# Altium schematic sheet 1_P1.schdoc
size 309 x 223 mm; Symbol: Sheet-Symbol_A4; Device: Sheet-Symbol_A4; Company: 嘉立创EDA; Version: V1.0; Page Size: A4; @Project Name: Magnetic robot_hkust_bi; @Page Count: 1; @Update Date: 2025-05-18; @Create Date: 2025-05-14; @Schematic Name: Schematic4; @Page No: 1; @Page Name: P1
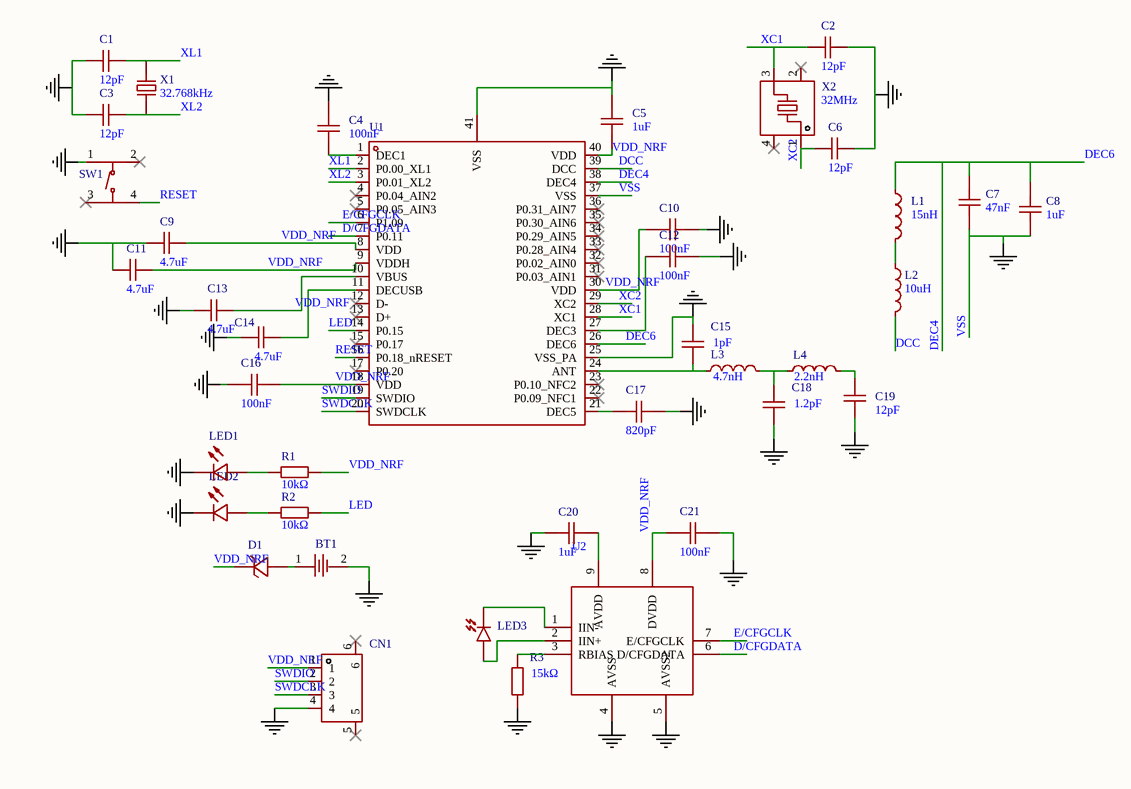
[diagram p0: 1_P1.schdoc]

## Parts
BT1  MY-927-01  [BAT-TH_MY-927-01]  (value not drawn)
C1  12pF  [C0402]
C2  12pF  [C0402]
C3  12pF  [C0402]
C4  100nF  [C0402]
C5  1uF  [C0402]
C6  12pF  [C0402]
C7  47nF  [C0402]
C8  1uF  [C0402]
C9  4.7uF  [C0402]
C10  100nF  [C0402]
C11  4.7uF  [C0402]
C12  100nF  [C0402]
C13  4.7uF  [C0402]
C14  4.7uF  [C0402]
C15  1pF  [C0402]
C16  100nF  [C0402]
C17  820pF  [C0402]
C18  1.2pF  [C0402]
C19  12pF  [C0402]
C20  1uF  [C0402]
C21  100nF  [C0402]
CN1  1.0-4PWB  [CONN-SMD_4P-P1.00_DEALON_1.0-4PWB]  (value not drawn)
D1  BZT52C3V3S  [SOD-323_L1.7-W1.3-LS2.6-RD]  (value not drawn)
L1  15nH  [IND-SMD_L1.0-W0.5-2]
L2  10uH  [IND-SMD_L2.5-W2.0]
L3  4.7nH  [IND-SMD_L1.0-W0.6]
L4  2.2nH  [IND-SMD_L1.0-W0.6]
LED1  NCD0603G1  [LED0603-RD_1]  (value not drawn)
LED2  NCD0603G1  [LED0603-RD_1]  (value not drawn)
LED3  VBPW34S  [SENSOR-SMD_L4.4-W3.9]  (value not drawn)
R1  10kΩ  [R0402]
R2  10kΩ  [R0402]
R3  15kΩ  [R0402]
SW1  TS-1187A-B-A-B  [SW-SMD_4P-L5.1-W5.1-P3.70-LS6.5-TL_H1.5]  (value not drawn)
U1  nRF52833-QDAA-R  [QFN-40_L5.0-W5.0-P0.40-TL-EP3.6]  (value not drawn)
U2  (no value)  [TS4231]
X1  32.768kHz  [OSC-SMD_L3.2-W1.5]
X2  32MHz  [CRYSTAL-SMD_4P-L2.0-W1.6-BL-2]

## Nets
VSS: BT1.2 C1.1 C2.2 C3.1 C4.2 C5.2 C6.2 C7.2 C8.2 C9.2 C10.2 C11.2 C12.2 C13.2 C14.1 C15.2 C16.1 C17.2 C18.1 C19.1 C20.1 C21.2 CN1.4 LED1.1(K) LED2.1(K) R3.1 SW1.1(A) U1.25(VSS_PA) U1.37(VSS) U1.41(VSS) U2.4(AVSS) U2.5(AVSS2)  [also labelled GND]
D/CFGDATA: U1.7(P0.11) U2.6(D/CFGDATA)
DCC: L2.2 U1.39(DCC)
DEC4: C7.1 C8.1 L1.2 U1.26(DEC6) U1.38(DEC4)  [also labelled DEC6]
E/CFGCLK: U1.6(P1.09) U2.7(E/CFGCLK)
LED: R2.2 U1.14(P0.15)
RESET: SW1.4(D) U1.16(P0.18_nRESET)
SWDCLK: CN1.3 U1.20(SWDCLK)
SWDIO: CN1.2 U1.19(SWDIO)
VDD_NRF: C5.1 C9.1 C10.1 C11.1 C13.1 C16.2 C21.1 CN1.1 D1.1(K) R1.2 U1.8(VDD) U1.9(VDDH) U1.10(VBUS) U1.18(VDD) U1.30(VDD) U1.40(VDD) U2.8(DVDD)
XC1: C2.1 U1.28(XC1) X2.3
XC2: C6.1 U1.29(XC2) X2.1
XL1: C1.2 U1.2(P0.00_XL1) X1.2
XL2: C3.2 U1.3(P0.01_XL2) X1.1
NetBT1_1: BT1.1 D1.2(A)
NetC4_1: C4.1 U1.1(DEC1)
NetC12_1: C12.1 U1.27(DEC3)
NetC14_2: C14.2 U1.11(DECUSB)
NetC15_1: C15.1 L3.1 U1.24(ANT)
NetC17_1: C17.1 U1.21(DEC5)
NetC18_2: C18.2 L3.2 L4.1
NetC19_2: C19.2 L4.2
NetC20_2: C20.2 U2.9(AVDD)
NetL1_1: L1.1 L2.1
NetLED1_2: LED1.2(A) R1.1
NetLED2_2: LED2.2(A) R2.1
NetLED3_1: LED3.1(A) U2.2(IIN+)
NetLED3_2: LED3.2(C) U2.1(IIN-)
NetR3_2: R3.2 U2.3(RBIAS)

Not connected (* = marked no-connect by the designer): CN1 5* 6*; SW1 2(B)* 3(C)*; U1 4(P0.04_AIN2)* 5(P0.05_AIN3)* 12(D-)* 13(D+)* 15(P0.17)* 17(P0.20)* 22(P0.09_NFC1)* 23(P0.10_NFC2)* 31(P0.03_AIN1)* 32(P0.02_AIN0)* 33(P0.28_AIN4)* 34(P0.29_AIN5)* 35(P0.30_AIN6)* 36(P0.31_AIN7)*; X2 2(GND)* 4(GND)*

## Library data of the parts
BT1 = MY-927-01: Manufacturer: MYOUNG(美阳); Add into BOM: yes; Connector Type: 电池扣; Battery Type: CR927
C1-C3 C6 C19 = GRM1555C1H120JA01D: Manufacturer: muRata(村田); Add into BOM: yes; Tolerance: ±5%; Voltage Rating: 50V; Temperature Coefficient: C0G
C4 C10 C12 C16 C21 = CL05B104KB54PNC: Manufacturer: SAMSUNG(三星); Add into BOM: yes; Tolerance: ±10%; Voltage Rated: 50V; Temperature Coefficient: X7R
C5 C8 C20 = CL05A105KA5NQNC: Manufacturer: SAMSUNG(三星); Add into BOM: yes; Tolerance: ±10%; Voltage Rated: 25V; Temperature Coefficient: X5R
C7 = CC0402KRX7R9BB473: Manufacturer: YAGEO(国巨); Add into BOM: yes; Tolerance: ±10%; Voltage Rated: 50V; Temperature Coefficient: X7R
C9 C11 C13 C14 = CL05A475MP5NRNC: Manufacturer: SAMSUNG(三星); Add into BOM: yes; Tolerance: ±20%; Voltage Rated: 10V; Temperature Coefficient: X5R
C15 = GJM1555C1H1R0WB01D: Manufacturer: muRata(村田); Add into BOM: yes; Voltage Rated: 50V; Temperature Coefficient: C0G
C17 = CC0402KRX7R9BB821: Manufacturer: YAGEO(国巨); Add into BOM: yes; Tolerance: ±10%; Voltage Rated: 50V; Temperature Coefficient: X7R
C18 = GJM1555C1H1R2WB01D: Manufacturer: muRata(村田); Add into BOM: yes; Voltage Rated: 50V; Temperature Coefficient: C0G
CN1 = 1.0-4PWB: Manufacturer: DEALON(德艺隆); Add into BOM: yes; Pins Structure: 1x4P; Pitch: 1mm; Reference Series: SH; Number of PINs Per Row: 4; Current Rating: 1A; Voltage Rating: 50V; Supplementary Features: 辅助焊脚; Z-Height of the Board: 2.9mm; X-Length of Bottom Edge on Board (Spacing Line): 6mm; Y-Width of Bottom Edge on Board: 5.03mm
D1 = BZT52C3V3S_C19077437: Manufacturer: 宏迦橙; Add into BOM: yes; Diode Configuration: 独立式; Zener Voltage (Nom): 3.3V; Reverse Leakage Current (Ir): 5uA@1V; Zener Voltage (Range): 3.1V~3.5V; Power Dissipation: 200mW; Zener Impedance (Zzt): 95Ω
L1 = LQW15AN15NG00D: Manufacturer: muRata(村田); Add into BOM: yes; Tolerance: ±2%; Rated Current: 460mA; DC Resistance (DCR): 160mΩ
L2 = FTC252012S100MBCA: Manufacturer: cjiang(长江微电); Add into BOM: yes; Tolerance: ±20%; Rated Current: 1.2A; Saturation Current (Isat): 1.6A; DC Resistance (DCR): 330mΩ; Type: 一体成型电感
L3 = LQW15AN4N7B00D: Manufacturer: muRata(村田); Add into BOM: yes; Rated Current: 750mA; DC Resistance (DCR): 70mΩ
L4 = LQW15AN2N2B80D: Manufacturer: muRata(村田); Add into BOM: yes; Rated Current: 2.53A; DC Resistance (DCR): 22mΩ
LED1 LED2 = NCD0603G1: Manufacturer: 国星光电; Symbol: FC-D1608UGK-520D10; Add into BOM: yes; Illumination Color: 翠绿色; Voltage - Forward(Vf): 2.6V~3.6V; Power(Watts): 72mW; Forward Current: 20mA; Wavelength - Dominant: 515nm~530nm; Luminous Intensity: 330mcd~900mcd; Viewing Angle: 130°
LED3 = VBPW34S: Manufacturer: VISHAY(威世); Add into BOM: yes; DC Reverse Voltage: 60V; Peak  Wavelength: 940nm; Spectral Range: 430nm~1100nm; Current Dark: 2nA
R1 R2 = 0402WGF1002TCE: Manufacturer: UNI-ROYAL(厚声); Add into BOM: yes; Tolerance: ±1%; Power(Watts): 62.5mW; Overload Voltage (Max): 50V; Temperature Coefficient: ±100ppm/
R3 = 0402WGF1502TCE: Manufacturer: UNI-ROYAL(厚声); Add into BOM: yes; Tolerance: ±1%; Power(Watts): 62.5mW; Overload Voltage (Max): 50V; Temperature Coefficient: ±100ppm/
SW1 = TS-1187A-B-A-B: Manufacturer: XKB Connectivity(中国星坤); Add into BOM: yes; Circuit: 单刀单掷; Actuator Style: 圆形按钮; Operating Force: 160gf; Switch Length: 5.1mm; Switch Height: 1.5mm; Strike Gundam: 不带; Contact Current: 50mA; Voltage Rating (DC): 12V; Actuator/Cap Color: 金色; With Lamp: 无; Mechanical Life: 10万次
U1 = nRF52833-QDAA-R: Manufacturer: NORDIC; Add into BOM: yes
U2 = TS4231: Add into BOM: yes
X1 = X321532768KGD2SI: Manufacturer: YXC(扬兴晶振); Add into BOM: yes; Crystal Type: 贴片晶振; Normal temperature Frequency Tolerance: ±20ppm; External load capacitor: 12.5pF
X2 = X201632MOB4SI: Manufacturer: YXC(扬兴晶振); Add into BOM: yes; Normal temperature Frequency Tolerance: ±10ppm; Load Capacitance: 12pF; Frequency Stability: ±20ppm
